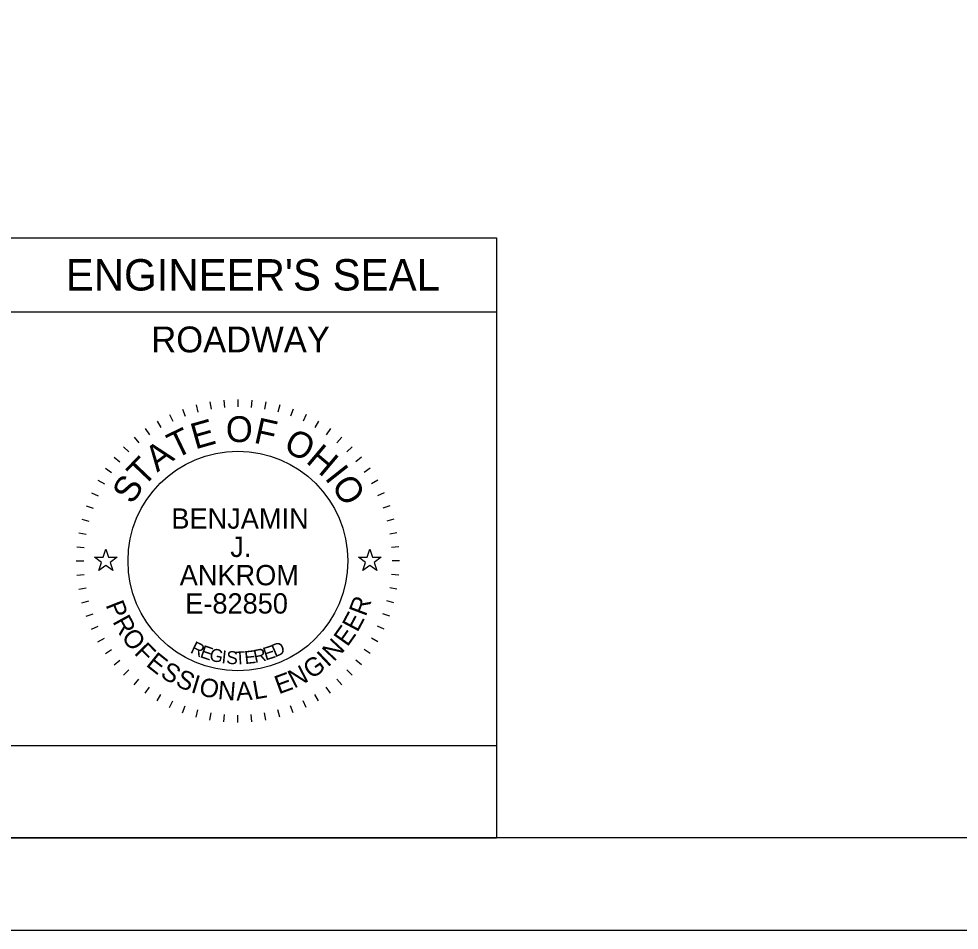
# Model space of a CAD drawing. Extents: x 0 to 68.9, y -26.1 to 22.
# Drawn here: x 23.81 to 28.91, y 0 to 4.94 of the extents above; entities that cross this region are included whole.
import ezdxf

# ---------------------------------------------------------------- set-up
doc = ezdxf.new("R2010")
doc.units = 0
for name, color, linetype in [('Default', 7, 'Continuous'), ('SH_Border', 7, 'Continuous'), ('SH_Cut_Line', 7, 'Continuous'), ('SH_Data', 7, 'Continuous')]:
    doc.layers.add(name, color=color, linetype=linetype)

msp = doc.modelspace()

# ---------------------------------------------------------------- linework, layer by layer
at = {"layer": 'Default'}
for points in [[(24.2236, 2.02), (24.2705, 2.02), (24.285, 2.0645), (24.2995, 2.02), (24.3464, 2.02), (24.3085, 1.9924), (24.323, 1.9478), (24.285, 1.9754), (24.247, 1.9478), (24.2615, 1.9924)], [(25.6536, 2.02), (25.7005, 2.02), (25.715, 2.0645), (25.7295, 2.02), (25.7764, 2.02), (25.7385, 1.9924), (25.753, 1.9478), (25.715, 1.9754), (25.677, 1.9478), (25.6915, 1.9924)]]:
    msp.add_lwpolyline(points, close=True, dxfattribs=at)
at = {"layer": 'SH_Border'}
msp.add_lwpolyline([(1.5, 21.5), (33.5, 21.5), (33.5, 0.5), (1.5, 0.5)], close=True, dxfattribs=at)
at = {"layer": 'SH_Cut_Line'}
msp.add_lwpolyline([(0, 0), (34, 0), (34, 22), (0, 22)], close=True, dxfattribs=at)
at = {"layer": 'SH_Data'}
for p, q in [((23.6, 3.75), (26.4, 3.75)), ((26.4, 3.75), (26.4, 0.5)), ((23.6, 3.35), (26.4, 3.35)), ((24.8481, 2.8617), (24.855, 2.8223)), ((24.9237, 2.8717), (24.9272, 2.8318)), ((25, 2.875), (25, 2.835)), ((25.0763, 2.8717), (25.0728, 2.8318)), ((25.1519, 2.8617), (25.145, 2.8223)), ((24.7007, 2.8222), (24.7144, 2.7846)), ((24.7735, 2.8452), (24.7839, 2.8065)), ((25.2265, 2.8452), (25.2161, 2.8065)), ((25.2993, 2.8222), (25.2856, 2.7846)), ((24.5625, 2.7578), (24.5825, 2.7231)), ((24.6302, 2.793), (24.6471, 2.7568)), ((25.3698, 2.793), (25.3529, 2.7568)), ((25.4375, 2.7578), (25.4175, 2.7231)), ((24.4981, 2.7168), (24.5211, 2.684)), ((25.5019, 2.7168), (25.4789, 2.684)), ((24.4376, 2.6703), (24.4633, 2.6396)), ((25.5624, 2.6703), (25.5367, 2.6396)), ((24.3813, 2.6187), (24.4096, 2.5904)), ((25.6187, 2.6187), (25.5904, 2.5904)), ((24.3297, 2.5624), (24.3604, 2.5367)), ((25.6703, 2.5624), (25.6396, 2.5367)), ((24.2832, 2.5019), (24.316, 2.4789)), ((25.7168, 2.5019), (25.684, 2.4789)), ((24.2422, 2.4375), (24.2769, 2.4175)), ((25.7578, 2.4375), (25.7231, 2.4175)), ((24.207, 2.3698), (24.2432, 2.3529)), ((25.793, 2.3698), (25.7568, 2.3529)), ((24.1778, 2.2993), (24.2154, 2.2856)), ((25.8222, 2.2993), (25.7846, 2.2856)), ((24.1548, 2.2265), (24.1935, 2.2161)), ((25.8452, 2.2265), (25.8065, 2.2161)), ((24.1383, 2.1519), (24.1777, 2.145)), ((25.8617, 2.1519), (25.8223, 2.145)), ((24.1283, 2.0763), (24.1682, 2.0728)), ((25.8717, 2.0763), (25.8318, 2.0728)), ((24.125, 2), (24.165, 2)), ((25.875, 2), (25.835, 2)), ((24.1283, 1.9237), (24.1682, 1.9272)), ((25.8717, 1.9237), (25.8318, 1.9272)), ((24.1383, 1.8481), (24.1777, 1.855)), ((25.8617, 1.8481), (25.8223, 1.855)), ((24.1548, 1.7735), (24.1935, 1.7839)), ((25.8452, 1.7735), (25.8065, 1.7839)), ((24.1778, 1.7007), (24.2154, 1.7144)), ((25.8222, 1.7007), (25.7846, 1.7144)), ((24.207, 1.6302), (24.2432, 1.6471)), ((25.793, 1.6302), (25.7568, 1.6471)), ((24.2422, 1.5625), (24.2769, 1.5825)), ((25.7578, 1.5625), (25.7231, 1.5825)), ((24.2832, 1.4981), (24.316, 1.5211)), ((25.7168, 1.4981), (25.684, 1.5211)), ((24.3297, 1.4376), (24.3604, 1.4633)), ((25.6703, 1.4376), (25.6396, 1.4633)), ((24.3813, 1.3813), (24.4096, 1.4096)), ((25.6187, 1.3813), (25.5904, 1.4096)), ((24.4376, 1.3297), (24.4633, 1.3604)), ((25.5624, 1.3297), (25.5367, 1.3604)), ((24.4981, 1.2832), (24.5211, 1.316)), ((24.5625, 1.2422), (24.5825, 1.2769)), ((25.4375, 1.2422), (25.4175, 1.2769)), ((25.5019, 1.2832), (25.4789, 1.316)), ((24.6302, 1.207), (24.6471, 1.2432)), ((25.3698, 1.207), (25.3529, 1.2432)), ((24.7007, 1.1778), (24.7144, 1.2154)), ((24.7735, 1.1548), (24.7839, 1.1935)), ((24.8481, 1.1383), (24.855, 1.1777)), ((25.1519, 1.1383), (25.145, 1.1777)), ((25.2265, 1.1548), (25.2161, 1.1935)), ((25.2993, 1.1778), (25.2856, 1.2154)), ((24.9237, 1.1283), (24.9272, 1.1682)), ((25, 1.125), (25, 1.165)), ((25.0763, 1.1283), (25.0728, 1.1682)), ((23.6, 0.5), (26.4, 0.5))]:
    msp.add_line(p, q, dxfattribs=at)
msp.add_lwpolyline([(23.6, 0.5), (23.6, 1), (26.4, 1), (26.4, 0.5)], close=True, dxfattribs=at)
msp.add_circle((25, 2), 0.595, dxfattribs=at)

# ---------------------------------------------------------------- texts
for s, height, p in [("ENGINEER'S SEAL", 0.17, (24.0676, 3.465)), ('ROADWAY', 0.14, (24.5311, 3.13)), ('BENJAMIN', 0.11, (24.6397, 2.1749)), ('J.', 0.11, (24.9587, 2.0216)), ('ANKROM', 0.11, (24.6849, 1.8684)), ('E-82850', 0.11, (24.7149, 1.7151))]:
    msp.add_text(s, height=height, dxfattribs=at).set_placement(p)
for s, height, rotation, p in [('E', 0.14, 15.7571, (24.7684, 2.6038)), ('O', 0.14, 359.7812, (24.9347, 2.6443)), ('F', 0.14, 347.4362, (25.0811, 2.6417)), ('T', 0.14, 25.7167, (24.6616, 2.5518)), ('O', 0.14, 332.2586, (25.2398, 2.6015)), ('A', 0.14, 36.4747, (24.5634, 2.4781)), ('H', 0.14, 319.9136, (25.3632, 2.5361)), ('T', 0.14, 46.4344, (24.4883, 2.3964)), ('I', 0.14, 308.367, (25.4665, 2.4483)), ('S', 0.14, 57.1924, (24.4281, 2.3014)), ('O', 0.14, 303.1491, (25.5021, 2.4089)), ('P', 0.1, 291.494, (24.2823, 1.7621)), ('R', 0.1, 69.2322, (25.6919, 1.6954)), ('R', 0.1, 298.7311, (24.319, 1.6717)), ('E', 0.1, 61.9951, (25.6476, 1.6098)), ('E', 0.1, 54.758, (25.5933, 1.5314)), ('O', 0.1, 306.4666, (24.3655, 1.5883)), ('N', 0.1, 47.0224, (25.5202, 1.4508)), ('F', 0.1, 314.7068, (24.4343, 1.4983)), ('R', 0.07, 334.487, (24.7375, 1.5051)), ('E', 0.07, 341.04, (24.7906, 1.4801)), ('E', 0.07, 17.6836, (25.1498, 1.4602)), ('D', 0.07, 23.3052, (25.201, 1.477)), ('E', 0.1, 321.4393, (24.4978, 1.4348)), ('G', 0.07, 347.4752, (24.8414, 1.4618)), ('I', 0.07, 353.7858, (24.9091, 1.4468)), ('S', 0.07, 356.8926, (24.9358, 1.4429)), ('T', 0.07, 3.0061, (24.9857, 1.4387)), ('E', 0.07, 6.0117, (25.0389, 1.4412)), ('R', 0.07, 11.9184, (25.0925, 1.4474)), ('G', 0.1, 35.0469, (25.3981, 1.357)), ('I', 0.1, 43.287, (25.4868, 1.4214)), ('S', 0.1, 328.6764, (24.5743, 1.3752)), ('N', 0.1, 27.3113, (25.3045, 1.3075)), ('S', 0.1, 335.9134, (24.6564, 1.3266)), ('I', 0.1, 343.1505, (24.7406, 1.2897)), ('E', 0.1, 20.0742, (25.2212, 1.277)), ('O', 0.1, 346.8859, (24.7839, 1.2751)), ('N', 0.1, 355.1261, (24.8888, 1.2517)), ('A', 0.1, 2.8617, (24.9923, 1.2437)), ('L', 0.1, 10.0987, (25.0894, 1.249))]:
    msp.add_text(s, height=height, rotation=rotation, dxfattribs=at).set_placement(p)

doc.saveas('drawing.dxf')
